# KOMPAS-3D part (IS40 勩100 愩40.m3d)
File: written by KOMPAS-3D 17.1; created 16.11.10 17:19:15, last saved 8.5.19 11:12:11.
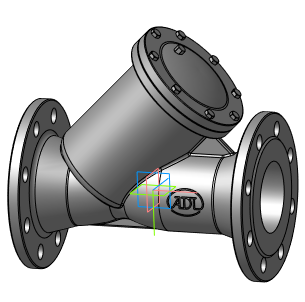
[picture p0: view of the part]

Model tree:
1. Плоскость XY
2. Плоскость ZX
3. Плоскость ZY
4. Ось X
5. Ось Y
6. Ось Z
7. Начало координат
8. Операция без истории:3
